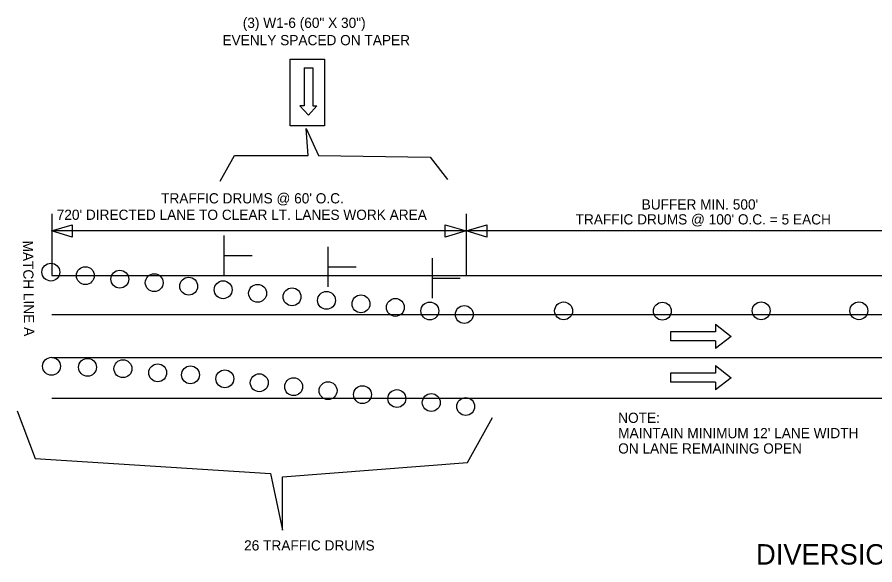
# Model space of a CAD drawing. Extents: x 37171 to 39457, y -18939 to -17445.
# Drawn here: x 37264 to 38020, y -18787 to -18304 of the extents above; entities that cross this region are included whole.
import ezdxf

# ---------------------------------------------------------------- set-up
doc = ezdxf.new("R2010")
doc.units = 0
for name, color, linetype in [('Default', 7, 'Continuous'), ('R_Const Phase 4', 7, 'Continuous'), ('R_Proposed Road Annot', 7, 'Continuous')]:
    doc.layers.add(name, color=color, linetype=linetype)

msp = doc.modelspace()

# ---------------------------------------------------------------- linework, layer by layer
at = {"layer": 'Default'}
for p, q in [((37516.99, -18348.65), (37516.99, -18382.11)), ((37516.99, -18348.65), (37524.44, -18348.65)), ((37524.44, -18348.65), (37524.44, -18382.11)), ((37516.99, -18382.11), (37513.26, -18382.11)), ((37513.26, -18382.11), (37520.71, -18390.28)), ((37520.71, -18390.28), (37528.17, -18382.11)), ((37524.44, -18382.11), (37528.17, -18382.11))]:
    msp.add_line(p, q, dxfattribs=at)
msp.add_lwpolyline([(37504.73, -18399.85), (37504.73, -18341.17), (37534.73, -18341.17), (37534.73, -18399.85)], close=True, dxfattribs=at)
for centre, radius in [((37293.88, -18528.7), 7.87), ((37324.22, -18531.81), 7.87), ((37354.56, -18534.93), 7.87), ((37384.9, -18538.04), 7.87), ((37415.24, -18541.16), 7.87), ((37445.58, -18544.27), 7.87), ((37475.92, -18547.39), 7.87), ((37506.26, -18550.5), 7.87), ((37536.6, -18553.62), 7.87), ((37566.94, -18556.73), 7.87), ((37597.28, -18559.84), 7.87), ((37627.62, -18562.96), 7.87), ((37657.96, -18566.07), 7.87), ((37745.41, -18562.91), 7.87), ((37832.41, -18563.12), 7.87), ((37919.4, -18562.82), 7.87), ((38005.47, -18562.8), 7.87), ((37294.43, -18611.72), 7.88), ((37326.16, -18612.62), 7.88), ((37357.33, -18613.85), 7.88), ((37387.93, -18617.45), 7.88), ((37416.78, -18619.26), 7.88), ((37447.08, -18622.75), 7.88), ((37477.38, -18626.24), 7.88), ((37507.68, -18629.73), 7.88), ((37537.98, -18633.22), 7.88), ((37568.28, -18636.7), 7.88), ((37598.58, -18640.19), 7.88), ((37628.88, -18643.68), 7.88), ((37659.18, -18647.17), 7.88)]:
    msp.add_circle(centre, radius, dxfattribs=at)
at = {"layer": 'R_Const Phase 4'}
for p, q in [((37446.46, -18531.75), (37446.46, -18496.48)), ((37538.04, -18541.75), (37538.04, -18506.48)), ((37446.97, -18514.2), (37471.04, -18514.2)), ((37629.83, -18551.75), (37629.83, -18516.48)), ((37538.55, -18524.2), (37562.62, -18524.2)), ((37294.7, -18531.75), (37659.51, -18531.75)), ((37630.34, -18534.2), (37654.41, -18534.2)), ((37659.51, -18531.75), (38034.84, -18531.75)), ((37294.7, -18566), (39041.74, -18566)), ((37879.16, -18581.32), (37839.63, -18581.32)), ((37839.63, -18581.32), (37839.63, -18589.38)), ((37879.16, -18574.61), (37879.16, -18581.32)), ((37879.16, -18574.61), (37893.11, -18585.35)), ((37893.11, -18585.35), (37879.16, -18596.1)), ((37879.16, -18589.38), (37839.63, -18589.38)), ((37879.16, -18589.38), (37879.16, -18596.1)), ((37294.7, -18603.85), (39041.74, -18603.85)), ((37879.16, -18611.06), (37879.16, -18617.78)), ((37879.16, -18611.06), (37893.11, -18621.81)), ((37879.16, -18617.78), (37839.63, -18617.78)), ((37839.63, -18617.78), (37839.63, -18625.84)), ((37879.16, -18625.84), (37839.63, -18625.84)), ((37893.11, -18621.81), (37879.16, -18632.56)), ((37879.16, -18625.84), (37879.16, -18632.56)), ((37294.7, -18639.85), (37659.51, -18639.85)), ((37659.51, -18639.85), (38050.05, -18639.85))]:
    msp.add_line(p, q, dxfattribs=at)
for points in [[(37442.99, -18448.65), (37455.6, -18425.82), (37520.33, -18425.82), (37518.64, -18402.19), (37529.57, -18425.82), (37627.92, -18427.45), (37643.05, -18447.02)], [(37264.17, -18651.02), (37279.96, -18692.89), (37487.3, -18706.17), (37497.83, -18756.21), (37497.83, -18709.23), (37660.91, -18696.59), (37682.67, -18656.92)]]:
    msp.add_lwpolyline(points, dxfattribs=at)
at = {"layer": 'R_Proposed Road Annot'}
for p, q in [((37294.7, -18477.39), (37294.7, -18531.75)), ((37659.51, -18477.39), (37659.51, -18531.75)), ((37294.43, -18492.49), (37312.68, -18487.01)), ((37312.68, -18487.01), (37312.68, -18497.96)), ((37641.26, -18497.96), (37641.26, -18487.01)), ((37641.26, -18487.01), (37659.51, -18492.49)), ((37659.51, -18492.49), (37677.77, -18487.01)), ((37677.77, -18487.01), (37677.77, -18497.96)), ((37659.51, -18492.49), (37294.43, -18492.49)), ((37312.68, -18497.96), (37294.43, -18492.49)), ((37659.51, -18492.49), (37641.26, -18497.96)), ((38092.26, -18492.49), (37659.51, -18492.49)), ((37677.77, -18497.96), (37659.51, -18492.49))]:
    msp.add_line(p, q, dxfattribs=at)

# ---------------------------------------------------------------- texts
for s, rotation, p in [('(3) W1-6 (60" X 30")', 0.00754, (37462.86, -18313.49)), ('EVENLY SPACED ON TAPER', 0.00754, (37444.97, -18328.77)), ('MATCH LINE A', 270.80593, (37269.12, -18501.01))]:
    msp.add_text(s, height=9, rotation=rotation, dxfattribs=at).set_placement(p)
for s, height, p in [("TRAFFIC DRUMS @ 60' O.C.", 9, (37390.93, -18468.17)), ("BUFFER MIN. 500'", 9, (37814.17, -18473.58)), ("720' DIRECTED LANE TO CLEAR LT. LANES WORK AREA", 9, (37299, -18482.68)), ("TRAFFIC DRUMS @ 100' O.C. = 5 EACH", 9, (37756.01, -18486.73)), ('NOTE:', 9, (37793.48, -18661.64)), ("MAINTAIN MINIMUM 12' LANE WIDTH", 9, (37793.48, -18675.14)), ('ON LANE REMAINING OPEN', 9, (37793.48, -18688.64)), ('26 TRAFFIC DRUMS', 9, (37464.03, -18774.09)), ('DIVERSION FOR LT. LANE WORK ZONE', 18, (37914.88, -18786.5))]:
    msp.add_text(s, height=height, dxfattribs=at).set_placement(p)

doc.saveas('drawing.dxf')
